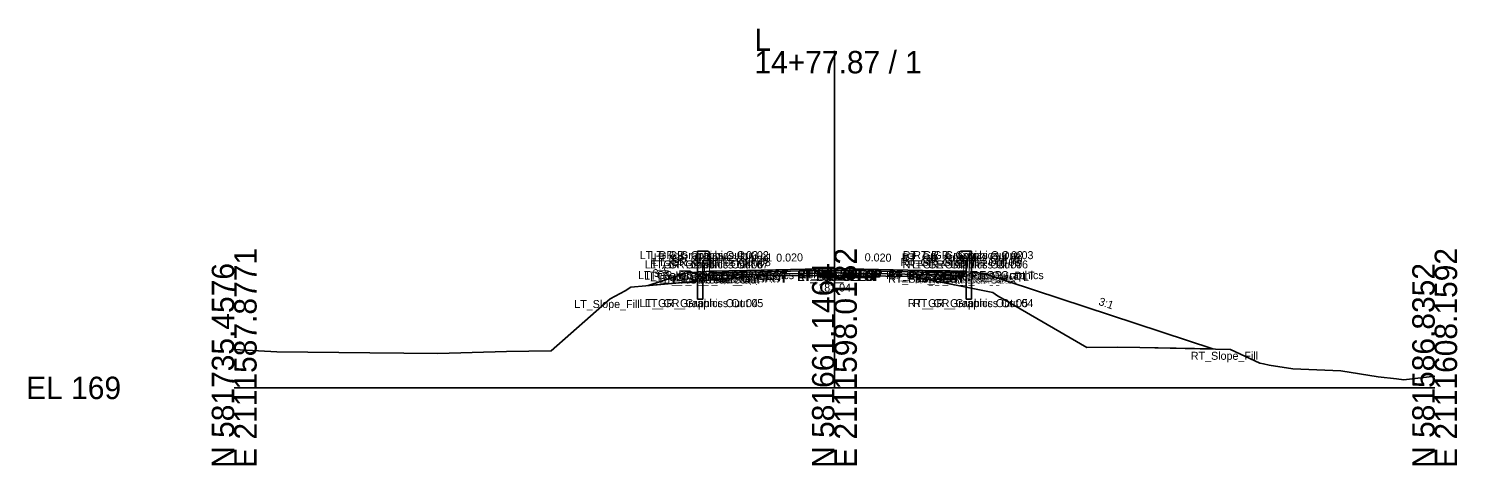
# Model space of a CAD drawing. Extents: x -486 to 1153, y -333 to 9539.
# Drawn here: x -25.7 to 152.8, y 4990.3 to 5044.9 of the extents above; entities that cross this region are included whole.
import ezdxf

# ---------------------------------------------------------------- set-up
doc = ezdxf.new("R2010")
doc.units = 0
for name, color, linetype in [('Default', 7, 'Continuous'), ('Exist Cross Section Cell', 7, 'Continuous'), ('Exist XS Ground Line', 7, 'Continuous'), ('Prop CMT Guardrail Graphics', 7, 'Continuous'), ('Prop CMT Pvmt Course 1', 7, 'Continuous'), ('Prop CMT Pvmt Course 2', 7, 'Continuous'), ('Prop CMT Pvmt Course 3', 7, 'Continuous'), ('Prop CMT Pvmt Surface', 7, 'Continuous'), ('Prop CMT Pvmt Surface Shoulder', 7, 'Continuous'), ('Prop CMT Shld Paved Course 1', 7, 'Continuous'), ('Prop CMT Shld Paved Course 2', 7, 'Continuous'), ('Prop CMT Shld Paved Course 3', 7, 'Continuous'), ('Prop CMT Slope Grass', 7, 'Continuous'), ('Prop CMT Subgrade Earthwork', 7, 'Continuous'), ('Prop XS Earthwork Shape', 7, 'Continuous'), ('Prop XS SE Text', 7, 'Continuous'), ('Prop XS Side Slope Text', 7, 'Continuous'), ('Scratch_Level_0', 7, 'Continuous')]:
    doc.layers.add(name, color=color, linetype=linetype)

msp = doc.modelspace()

# ---------------------------------------------------------------- linework, layer by layer
at = {"layer": 'Exist Cross Section Cell'}
for p, q in [((75, 5000), (75, 5042.11)), ((0, 5000), (75, 5000)), ((75, 5000), (150, 5000))]:
    msp.add_line(p, q, dxfattribs=at)
at = {"layer": 'Exist XS Ground Line'}
for p, q in [((49.57, 5012.59), (64.55, 5013.94)), ((64.55, 5013.94), (65.05, 5014)), ((65.05, 5014), (74.81, 5014.04)), ((74.81, 5014.04), (84.76, 5013.91)), ((84.76, 5013.91), (94.77, 5011.93)), ((46.99, 5011.15), (48.86, 5012.14)), ((48.86, 5012.14), (49.57, 5012.59)), ((94.77, 5011.93), (95.39, 5011.5)), ((95.39, 5011.5), (96.14, 5011.08)), ((39.61, 5004.63), (46.99, 5011.15)), ((96.14, 5011.08), (106.55, 5005.06)), ((0, 5004.79), (5.32, 5004.5)), ((5.32, 5004.5), (16.94, 5004.36)), ((16.94, 5004.36), (25.44, 5004.29)), ((25.44, 5004.29), (34.03, 5004.56)), ((34.03, 5004.56), (39.61, 5004.63)), ((106.55, 5005.06), (110.41, 5005.07)), ((110.41, 5005.07), (113.15, 5005.05)), ((113.15, 5005.05), (124.48, 5004.81)), ((124.48, 5004.81), (128.14, 5003.07)), ((128.14, 5003.07), (128.63, 5003.02)), ((128.63, 5003.02), (129.33, 5002.84)), ((129.33, 5002.84), (132.28, 5002.39)), ((132.28, 5002.39), (138.28, 5002.12)), ((138.28, 5002.12), (142.93, 5001.36)), ((142.93, 5001.36), (145.21, 5001.14)), ((145.21, 5001.14), (146.13, 5001.01)), ((146.13, 5001.01), (150, 5001.48))]:
    msp.add_line(p, q, dxfattribs=at)
at = {"layer": 'Prop CMT Guardrail Graphics'}
for points in [[(57.88, 5011.09), (57.88, 5017.09)], [(57.88, 5017.09), (59.21, 5017.09), (59.48, 5016.8)], [(59.48, 5016.8), (59.21, 5016.51)], [(92.12, 5017.09), (90.79, 5017.09), (90.52, 5016.8)], [(90.52, 5016.8), (90.79, 5016.51)], [(92.12, 5011.09), (92.12, 5017.09)], [(59.48, 5016.22), (59.21, 5015.93), (58.55, 5015.93)], [(58.55, 5015.93), (58.55, 5011.09)], [(59.21, 5016.51), (59.48, 5016.22)], [(90.79, 5016.51), (90.52, 5016.22)], [(90.52, 5016.22), (90.79, 5015.93), (91.45, 5015.93)], [(91.45, 5015.93), (91.45, 5011.09)], [(58.55, 5011.09), (57.88, 5011.09)], [(91.45, 5011.09), (92.12, 5011.09)]]:
    msp.add_lwpolyline(points, dxfattribs=at)
at = {"layer": 'Prop CMT Pvmt Course 1'}
for points in [[(75, 5014.91), (64, 5014.69)], [(64, 5014.48), (75, 5014.7)], [(64, 5014.69), (64, 5014.48)], [(75, 5014.7), (75, 5014.91)], [(75, 5014.91), (86, 5014.69)], [(75, 5014.7), (75, 5014.91)], [(86, 5014.48), (75, 5014.7)], [(86, 5014.69), (86, 5014.48)]]:
    msp.add_lwpolyline(points, dxfattribs=at)
msp.add_lwpolyline([(75, 5014.7), (75, 5014.78), (75, 5014.78), (75, 5014.7)], close=True, dxfattribs=at)
msp.add_lwpolyline([(75, 5014.7), (75, 5014.78), (75, 5014.78), (75, 5014.7)], close=True, dxfattribs=at)
at = {"layer": 'Prop CMT Pvmt Course 2'}
for points in [[(75, 5014.7), (64, 5014.48)], [(64, 5014.48), (64, 5014.15)], [(64, 5014.15), (75, 5014.37)], [(75, 5014.37), (75, 5014.7)], [(75, 5014.37), (75, 5014.7)], [(75, 5014.7), (86, 5014.48)], [(86, 5014.15), (75, 5014.37)], [(86, 5014.48), (86, 5014.15)]]:
    msp.add_lwpolyline(points, dxfattribs=at)
at = {"layer": 'Prop CMT Pvmt Course 3'}
for points in [[(75, 5014.37), (64, 5014.15)], [(64, 5014.15), (64, 5014.15)], [(75, 5014.37), (75, 5014.37)], [(75, 5014.37), (86, 5014.15)], [(75, 5014.37), (75, 5014.37)], [(86, 5014.15), (86, 5014.15)]]:
    msp.add_lwpolyline(points, dxfattribs=at)
at = {"layer": 'Prop CMT Pvmt Surface'}
for points in [[(75, 5014.91), (64, 5014.69)], [(75, 5014.91), (86, 5014.69)]]:
    msp.add_lwpolyline(points, dxfattribs=at)
at = {"layer": 'Prop CMT Pvmt Surface Shoulder'}
for points in [[(64, 5014.69), (59.58, 5014.6)], [(86, 5014.69), (90.42, 5014.6)]]:
    msp.add_lwpolyline(points, dxfattribs=at)
at = {"layer": 'Prop CMT Shld Paved Course 1'}
for points in [[(64, 5014.69), (59.58, 5014.6), (59.37, 5014.39)], [(59.37, 5014.39), (64, 5014.48)], [(64, 5014.48), (64, 5014.69)], [(86, 5014.69), (90.42, 5014.6), (90.63, 5014.39)], [(86, 5014.48), (86, 5014.69)], [(90.63, 5014.39), (86, 5014.48)]]:
    msp.add_lwpolyline(points, dxfattribs=at)
at = {"layer": 'Prop CMT Shld Paved Course 2'}
for points in [[(64, 5014.48), (59.37, 5014.39), (59.03, 5014.05)], [(59.03, 5014.05), (64, 5014.15)], [(64, 5014.15), (64, 5014.48)], [(86, 5014.48), (90.63, 5014.39), (90.97, 5014.05)], [(86, 5014.15), (86, 5014.48)], [(90.97, 5014.05), (86, 5014.15)]]:
    msp.add_lwpolyline(points, dxfattribs=at)
at = {"layer": 'Prop CMT Shld Paved Course 3'}
for points in [[(64, 5014.15), (59.03, 5014.05)], [(59.03, 5014.05), (59.03, 5014.05), (59.03, 5014.05)], [(64, 5014.15), (64, 5014.15)], [(86, 5014.15), (90.97, 5014.05)], [(86, 5014.15), (86, 5014.15)], [(90.97, 5014.05), (90.97, 5014.05), (90.97, 5014.05)]]:
    msp.add_lwpolyline(points, dxfattribs=at)
at = {"layer": 'Prop CMT Slope Grass'}
for points in [[(56.48, 5014.35), (51.74, 5012.79)], [(59.48, 5014.59), (56.48, 5014.35)], [(59.58, 5014.6), (59.48, 5014.59)], [(90.42, 5014.6), (90.52, 5014.59)], [(90.52, 5014.59), (93.52, 5014.35)], [(93.52, 5014.35), (122.29, 5004.86)]]:
    msp.add_lwpolyline(points, dxfattribs=at)
at = {"layer": 'Prop CMT Subgrade Earthwork'}
for points in [[(59.03, 5014.05), (58.56, 5014.52)], [(64, 5014.15), (59.03, 5014.05)], [(75, 5014.37), (64, 5014.15)], [(75, 5014.37), (86, 5014.15)], [(86, 5014.15), (90.97, 5014.05)], [(90.97, 5014.05), (91.44, 5014.52)]]:
    msp.add_lwpolyline(points, dxfattribs=at)
at = {"layer": 'Prop XS Earthwork Shape'}
msp.add_lwpolyline([(64.55, 5013.94), (65.05, 5014), (74.81, 5014.04), (84.76, 5013.91), (94.77, 5011.93), (95.39, 5011.5), (96.14, 5011.08), (106.55, 5005.06), (110.41, 5005.07), (113.15, 5005.05), (122.29, 5004.86), (93.52, 5014.35), (91.44, 5014.52), (90.97, 5014.05), (86, 5014.15), (75, 5014.37), (64, 5014.15), (59.03, 5014.05), (58.56, 5014.52), (56.48, 5014.35), (51.74, 5012.79)], close=True, dxfattribs=at)

# ---------------------------------------------------------------- texts
at = {"layer": 'Default'}
for s, height, p in [('183.04', 1, (72.98, 5012.04)), ('-', 0.0001, (0, 5000))]:
    msp.add_text(s, height=height, dxfattribs=at).set_placement(p)
at = {"layer": 'Exist Cross Section Cell'}
for s, p in [('L', (65, 5042.11)), ('14+77.87 / 1', (65, 5039.31)), ('EL 169', (-26, 4998.6))]:
    msp.add_text(s, height=2.8, dxfattribs=at).set_placement(p)
for s, p in [('E 2111587.8771', (2.8, 4990)), ('E 2111598.0182', (77.8, 4990)), ('E 2111608.1592', (152.8, 4990)), ('N 581735.4576', (0, 4990)), ('N 581661.1464', (75, 4990)), ('N 581586.8352', (150, 4990))]:
    msp.add_text(s, height=2.8, rotation=90, dxfattribs=at).set_placement(p)
at = {"layer": 'Prop XS SE Text'}
for rotation, p in [(1.1458, (67.73, 5015.76)), (358.8542, (78.77, 5015.83))]:
    msp.add_text('0.020', height=1, rotation=rotation, dxfattribs=at).set_placement(p)
at = {"layer": 'Prop XS Side Slope Text'}
for rotation, p in [(18.2629, (52.53, 5013.76)), (341.7371, (107.92, 5010.39))]:
    msp.add_text('3:1', height=1, rotation=rotation, dxfattribs=at).set_placement(p)
at = {"layer": 'Scratch_Level_0'}
for s, p in [('LT_GR_Graphics Out 03', (50.66, 5016.09)), ('LT_GR_Graphics Out 02', (52.01, 5016.09)), ('LT_GR_Graphics Out 01', (52.43, 5015.8)), ('RT_GR_Graphics Out 01', (83.4, 5015.8)), ('RT_GR_Graphics Out 02', (83.53, 5016.09)), ('RT_GR_Graphics Out 03', (84.85, 5016.09)), ('LT_GR_Graphics Out 06', (51.32, 5014.93)), ('LT_GR_Graphics Out 07', (51.97, 5014.93)), ('LT_GR_Graphics Out 09', (51.99, 5015.51)), ('LT_GR_Graphics Out 08', (52.25, 5015.22)), ('RT_GR_Graphics Out 08', (83.23, 5015.22)), ('RT_GR_Graphics Out 07', (83.49, 5014.93)), ('RT_GR_Graphics Out 09', (83.5, 5015.51)), ('RT_GR_Graphics Out 06', (84.17, 5014.93)), ('LT_GS_OS_GR_Face_Graphics', (50.48, 5013.59)), ('LT_Sub_Trench_Out_DLT', (51.21, 5013.52)), ('LT_GS_OS_CTL', (51.95, 5013.35)), ('LT_Sub_Trench_Out', (53.14, 5013.05)), ('LT_PS3_Shelf_Out', (53.69, 5013.05)), ('LT_PS3_OEOP', (54.82, 5013.05)), ('LT_PS2_OEOP', (55.16, 5013.39)), ('LT_PS1_OEOP', (55.49, 5013.6)), ('LT_PV2_OEOT', (59.75, 5013.48)), ('LT_PV3_OEOT', (59.75, 5013.15)), ('LT_Sub_OEOT', (59.77, 5013.15)), ('LT_PV1_OEOT', (59.87, 5013.69)), ('RT_PV2_OEEOP', (70.33, 5013.7)), ('RT_PV3_OEEOP', (70.33, 5013.37)), ('RT_Sub_OEEOP', (70.36, 5013.37)), ('LT_PV2_OEEOP', (70.39, 5013.7)), ('LT_PV3_OEEOP', (70.39, 5013.37)), ('LT_Sub_OEEOP', (70.42, 5013.37)), ('RT_PV1_OEEOP', (70.45, 5013.78)), ('LT_PV1_OEEOP', (70.51, 5013.78)), ('RT_PV2_IEEOP', (70.71, 5013.7)), ('LT_PV2_IEEOP', (70.77, 5013.7)), ('RT_PV1_IEEOP', (70.83, 5013.78)), ('LT_PV1_IEEOP', (70.89, 5013.78)), ('PV2_PGL', (72.35, 5013.7)), ('PV1_PGL', (72.47, 5013.91)), ('RT_GS_OS_GR_Face_Graphics', (81.45, 5013.59)), ('RT_PV2_OEOT', (81.69, 5013.48)), ('RT_PV3_OEOT', (81.69, 5013.15)), ('RT_Sub_OEOT', (81.71, 5013.15)), ('RT_PV1_OEOT', (81.81, 5013.69)), ('RT_Sub_Trench_Out_DLT', (84.03, 5013.52)), ('RT_Sub_Trench_Out', (85.02, 5013.05)), ('RT_PS3_Shelf_Out', (85.57, 5013.05)), ('RT_PS1_OEOP', (86.26, 5013.6)), ('RT_PS2_OEOP', (86.36, 5013.39)), ('RT_PS3_OEOP', (86.7, 5013.05)), ('RT_GS_OS_CTL', (88.92, 5013.35)), ('LT_Slope_Fill', (42.49, 5009.98)), ('LT_GR_Graphics Out 04', (50.65, 5010.09)), ('LT_GR_Graphics Out 05', (51.32, 5010.09)), ('RT_GR_Graphics Out 05', (84.17, 5010.09)), ('RT_GR_Graphics Out 04', (84.83, 5010.09)), ('RT_Slope_Fill', (119.53, 5003.51))]:
    msp.add_text(s, height=1, dxfattribs=at).set_placement(p)

doc.saveas('drawing.dxf')
